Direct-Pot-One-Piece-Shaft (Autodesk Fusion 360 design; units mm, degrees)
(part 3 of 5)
sketch "Restore cam service opening after obsolete bore closure" plane through (23.9, 0, 0) normal (1, 0, 0) x axis (0, 0, -1)
  line L1 (-42.2047, 46.7373) -> (-43.8497, 47.5044)
  line L2 (-40.5875, 45.9133) -> (-42.2047, 46.7373)
  line L3 (-39, 45.0333) -> (-40.5875, 45.9133)
  line L4 (-37.4442, 44.0985) -> (-39, 45.0333)
  line L5 (-35.922, 43.11) -> (-37.4442, 44.0985)
  line L6 (-34.4352, 42.0689) -> (-35.922, 43.11)
  line L7 (-32.9856, 40.9766) -> (-34.4352, 42.0689)
  line L8 (-31.575, 39.8343) -> (-32.9856, 40.9766)
  line L9 (-30.2052, 38.6435) -> (-31.575, 39.8343)
  line L10 (-28.8778, 37.4057) -> (-30.2052, 38.6435)
  line L11 (-27.5943, 36.1222) -> (-28.8778, 37.4057)
  line L12 (-26.3565, 34.7948) -> (-27.5943, 36.1222)
  line L13 (-25.1657, 33.425) -> (-26.3565, 34.7948)
  line L14 (-24.0234, 32.0144) -> (-25.1657, 33.425)
  line L15 (-22.9311, 30.5648) -> (-24.0234, 32.0144)
  line L16 (-21.89, 29.078) -> (-22.9311, 30.5648)
  line L17 (-20.9015, 27.5558) -> (-21.89, 29.078)
  line L18 (-19.9667, 26) -> (-20.9015, 27.5558)
  line L19 (-19.0867, 24.4125) -> (-19.9667, 26)
  line L20 (-18.2627, 22.7953) -> (-19.0867, 24.4125)
  line L21 (-17.4956, 21.1503) -> (-18.2627, 22.7953)
  line L22 (-16.7864, 19.4795) -> (-17.4956, 21.1503)
  line L23 (-16.136, 17.785) -> (-16.7864, 19.4795)
  line L24 (-15.5451, 16.0689) -> (-16.136, 17.785)
  line L25 (-15.0144, 14.3331) -> (-15.5451, 16.0689)
  line L26 (-14.5446, 12.5799) -> (-15.0144, 14.3331)
  line L27 (-14.1363, 10.8114) -> (-14.5446, 12.5799)
  line L28 (-13.79, 9.0297) -> (-14.1363, 10.8114)
  line L29 (-13.5061, 7.237) -> (-13.79, 9.0297)
  line L30 (-13.2849, 5.4355) -> (-13.5061, 7.237)
  line L31 (-13.1267, 3.6273) -> (-13.2849, 5.4355)
  line L32 (-13.0317, 1.8148) -> (-13.1267, 3.6273)
  line L33 (-13, 0) -> (-13.0317, 1.8148)
  line L34 (-13.0317, -1.8148) -> (-13, 0)
  line L35 (-13.1267, -3.6273) -> (-13.0317, -1.8148)
  line L36 (-13.2849, -5.4355) -> (-13.1267, -3.6273)
  line L37 (-13.5061, -7.237) -> (-13.2849, -5.4355)
  line L38 (-13.79, -9.0297) -> (-13.5061, -7.237)
  line L39 (-14.1363, -10.8114) -> (-13.79, -9.0297)
  line L40 (-14.5446, -12.5799) -> (-14.1363, -10.8114)
  line L41 (-15.0144, -14.3331) -> (-14.5446, -12.5799)
  line L42 (-15.5451, -16.0689) -> (-15.0144, -14.3331)
  line L43 (-16.136, -17.785) -> (-15.5451, -16.0689)
  line L44 (-16.7864, -19.4795) -> (-16.136, -17.785)
  line L45 (-17.4956, -21.1503) -> (-16.7864, -19.4795)
  line L46 (-18.2627, -22.7953) -> (-17.4956, -21.1503)
  line L47 (-19.0867, -24.4125) -> (-18.2627, -22.7953)
  line L48 (-19.9667, -26) -> (-19.0867, -24.4125)
  line L49 (-20.9015, -27.5558) -> (-19.9667, -26)
  line L50 (-21.89, -29.078) -> (-20.9015, -27.5558)
  line L51 (-22.9311, -30.5648) -> (-21.89, -29.078)
  line L52 (-24.0234, -32.0144) -> (-22.9311, -30.5648)
  line L53 (-25.1657, -33.425) -> (-24.0234, -32.0144)
  line L54 (-26.3565, -34.7948) -> (-25.1657, -33.425)
  line L55 (-27.5943, -36.1222) -> (-26.3565, -34.7948)
  line L56 (-28.8778, -37.4057) -> (-27.5943, -36.1222)
  line L57 (-30.2052, -38.6435) -> (-28.8778, -37.4057)
  line L58 (-31.575, -39.8343) -> (-30.2052, -38.6435)
  line L59 (-32.9856, -40.9766) -> (-31.575, -39.8343)
  line L60 (-34.4352, -42.0689) -> (-32.9856, -40.9766)
  line L61 (-35.922, -43.11) -> (-34.4352, -42.0689)
  line L62 (-37.4442, -44.0985) -> (-35.922, -43.11)
  line L63 (-39, -45.0333) -> (-37.4442, -44.0985)
  line L64 (-40.5875, -45.9133) -> (-39, -45.0333)
  line L65 (-42.2047, -46.7373) -> (-40.5875, -45.9133)
  line L66 (-43.8497, -47.5044) -> (-42.2047, -46.7373)
  line L67 (-54.4248, -23.7522) -> (-43.8497, -47.5044)
  line L68 (-53.6024, -23.3686) -> (-54.4248, -23.7522)
  line L69 (-52.7937, -22.9566) -> (-53.6024, -23.3686)
  line L70 (-52, -22.5167) -> (-52.7937, -22.9566)
  line L71 (-51.2221, -22.0493) -> (-52, -22.5167)
  line L72 (-50.461, -21.555) -> (-51.2221, -22.0493)
  line L73 (-49.7176, -21.0344) -> (-50.461, -21.555)
  line L74 (-48.9928, -20.4883) -> (-49.7176, -21.0344)
  line L75 (-48.2875, -19.9172) -> (-48.9928, -20.4883)
  line L76 (-47.6026, -19.3218) -> (-48.2875, -19.9172)
  line L77 (-46.9389, -18.7028) -> (-47.6026, -19.3218)
  line L78 (-46.2972, -18.0611) -> (-46.9389, -18.7028)
  line L79 (-45.6782, -17.3974) -> (-46.2972, -18.0611)
  line L80 (-45.0828, -16.7125) -> (-45.6782, -17.3974)
  line L81 (-44.5117, -16.0072) -> (-45.0828, -16.7125)
  line L82 (-43.9656, -15.2824) -> (-44.5117, -16.0072)
  line L83 (-43.445, -14.539) -> (-43.9656, -15.2824)
  line L84 (-42.9507, -13.7779) -> (-43.445, -14.539)
  line L85 (-42.4833, -13) -> (-42.9507, -13.7779)
  line L86 (-42.0434, -12.2063) -> (-42.4833, -13)
  line L87 (-41.6314, -11.3976) -> (-42.0434, -12.2063)
  line L88 (-41.2478, -10.5752) -> (-41.6314, -11.3976)
  line L89 (-40.8932, -9.7398) -> (-41.2478, -10.5752)
  line L90 (-40.568, -8.8925) -> (-40.8932, -9.7398)
  line L91 (-40.2725, -8.0344) -> (-40.568, -8.8925)
  line L92 (-40.0072, -7.1666) -> (-40.2725, -8.0344)
  line L93 (-39.7723, -6.29) -> (-40.0072, -7.1666)
  line L94 (-39.5682, -5.4057) -> (-39.7723, -6.29)
  line L95 (-39.395, -4.5149) -> (-39.5682, -5.4057)
  line L96 (-39.253, -3.6185) -> (-39.395, -4.5149)
  line L97 (-39.1424, -2.7177) -> (-39.253, -3.6185)
  line L98 (-39.0633, -1.8137) -> (-39.1424, -2.7177)
  line L99 (-39.0158, -0.9074) -> (-39.0633, -1.8137)
  line L100 (-39, 0) -> (-39.0158, -0.9074)
  line L101 (-39.0158, 0.9074) -> (-39, 0)
  line L102 (-39.0633, 1.8137) -> (-39.0158, 0.9074)
  line L103 (-39.1424, 2.7177) -> (-39.0633, 1.8137)
  line L104 (-39.253, 3.6185) -> (-39.1424, 2.7177)
  line L105 (-39.395, 4.5149) -> (-39.253, 3.6185)
  line L106 (-39.5682, 5.4057) -> (-39.395, 4.5149)
  line L107 (-39.7723, 6.29) -> (-39.5682, 5.4057)
  line L108 (-40.0072, 7.1666) -> (-39.7723, 6.29)
  line L109 (-40.2725, 8.0344) -> (-40.0072, 7.1666)
  line L110 (-40.568, 8.8925) -> (-40.2725, 8.0344)
  line L111 (-40.8932, 9.7398) -> (-40.568, 8.8925)
  line L112 (-41.2478, 10.5752) -> (-40.8932, 9.7398)
  line L113 (-41.6314, 11.3976) -> (-41.2478, 10.5752)
  line L114 (-42.0434, 12.2063) -> (-41.6314, 11.3976)
  line L115 (-42.4833, 13) -> (-42.0434, 12.2063)
  line L116 (-42.9507, 13.7779) -> (-42.4833, 13)
  line L117 (-43.445, 14.539) -> (-42.9507, 13.7779)
  line L118 (-43.9656, 15.2824) -> (-43.445, 14.539)
  line L119 (-44.5117, 16.0072) -> (-43.9656, 15.2824)
  line L120 (-45.0828, 16.7125) -> (-44.5117, 16.0072)
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extrude "Extrude47" cut sketch "Restore cam service opening after obsolete bore closure" along normal blind 12.2
work_plane "WorkPlane48" AlongDistance -15.4 ExtraOffset 0
sketch "Fill former M5 stop nut pocket" plane through (-15.4, 0, 0) normal (1, 0, 0) x axis (0, 0, -1)
  circle C1 centre (-79.6754, -33.9652) radius 4.9
extrude "Extrude48" add sketch "Fill former M5 stop nut pocket" along normal blind 6.4
work_plane "WorkPlane49" AlongDistance -36 ExtraOffset 0
sketch "Fill former M5 stop bore" plane through (-36, 0, 0) normal (1, 0, 0) x axis (0, 0, -1)
  circle C1 centre (-79.6754, -33.9652) radius 2.71
extrude "Extrude49" add sketch "Fill former M5 stop bore" along normal blind 27
work_plane "WorkPlane50" AlongDistance -36.1 ExtraOffset 0
sketch "M3 stop reinforcement bore" plane through (-36.1, 0, 0) normal (1, 0, 0) x axis (0, 0, -1)
  circle C1 centre (-79.6754, -33.9652) radius 1.7
extrude "Extrude50" cut sketch "M3 stop reinforcement bore" along normal blind 27.2
work_plane "WorkPlane51" AlongDistance -13.5 ExtraOffset 0
sketch "Captive M3 locknut stop pocket" plane through (-13.5, 0, 0) normal (1, 0, 0) x axis (0, 0, -1)
  line L1 (-82.5754, -32.2908) -> (-79.6754, -30.6165)
  line L2 (-82.5754, -35.6395) -> (-82.5754, -32.2908)
  line L3 (-79.6754, -37.3138) -> (-82.5754, -35.6395)
  line L4 (-76.7754, -35.6395) -> (-79.6754, -37.3138)
  line L5 (-76.7754, -32.2908) -> (-76.7754, -35.6395)
  line L6 (-79.6754, -30.6165) -> (-76.7754, -32.2908)
extrude "Extrude51" cut sketch "Captive M3 locknut stop pocket" along normal blind 4.6
work_plane "WorkPlane52" AlongDistance -15.4 ExtraOffset 0
sketch "Fill former M5 stop nut pocket (1)" plane through (-15.4, 0, 0) normal (1, 0, 0) x axis (0, 0, -1)
  circle C1 centre (-79.6754, 33.9652) radius 4.9
extrude "Extrude52" add sketch "Fill former M5 stop nut pocket (1)" along normal blind 6.4
work_plane "WorkPlane53" AlongDistance -36 ExtraOffset 0
sketch "Fill former M5 stop bore (1)" plane through (-36, 0, 0) normal (1, 0, 0) x axis (0, 0, -1)
  circle C1 centre (-79.6754, 33.9652) radius 2.71
extrude "Extrude53" add sketch "Fill former M5 stop bore (1)" along normal blind 27
work_plane "WorkPlane54" AlongDistance -36.1 ExtraOffset 0
sketch "M3 stop reinforcement bore (1)" plane through (-36.1, 0, 0) normal (1, 0, 0) x axis (0, 0, -1)
  circle C1 centre (-79.6754, 33.9652) radius 1.7
extrude "Extrude54" cut sketch "M3 stop reinforcement bore (1)" along normal blind 27.2
work_plane "WorkPlane55" AlongDistance -13.5 ExtraOffset 0
sketch "Captive M3 locknut stop pocket (1)" plane through (-13.5, 0, 0) normal (1, 0, 0) x axis (0, 0, -1)
  line L1 (-82.5754, 35.6395) -> (-79.6754, 37.3138)
  line L2 (-82.5754, 32.2908) -> (-82.5754, 35.6395)
  line L3 (-79.6754, 30.6165) -> (-82.5754, 32.2908)
  line L4 (-76.7754, 32.2908) -> (-79.6754, 30.6165)
  line L5 (-76.7754, 35.6395) -> (-76.7754, 32.2908)
  line L6 (-79.6754, 37.3138) -> (-76.7754, 35.6395)
extrude "Extrude55" cut sketch "Captive M3 locknut stop pocket (1)" along normal blind 4.6
work_plane "WorkPlane56" AlongDistance -17.5 ExtraOffset 0
sketch "Recess M3 locknut to keep bolt inside stop" plane through (-17.5, 0, 0) normal (1, 0, 0) x axis (0, 0, -1)
  line L1 (-82.5754, -32.2908) -> (-79.6754, -30.6165)
  line L2 (-82.5754, -35.6395) -> (-82.5754, -32.2908)
  line L3 (-79.6754, -37.3138) -> (-82.5754, -35.6395)
  line L4 (-76.7754, -35.6395) -> (-79.6754, -37.3138)
  line L5 (-76.7754, -32.2908) -> (-76.7754, -35.6395)
  line L6 (-79.6754, -30.6165) -> (-76.7754, -32.2908)
extrude "Extrude56" cut sketch "Recess M3 locknut to keep bolt inside stop" along normal blind 4.01
work_plane "WorkPlane57" AlongDistance -17.5 ExtraOffset 0
sketch "Recess M3 locknut to keep bolt inside stop (1)" plane through (-17.5, 0, 0) normal (1, 0, 0) x axis (0, 0, -1)
  line L1 (-82.5754, 35.6395) -> (-79.6754, 37.3138)
  line L2 (-82.5754, 32.2908) -> (-82.5754, 35.6395)
  line L3 (-79.6754, 30.6165) -> (-82.5754, 32.2908)
  line L4 (-76.7754, 32.2908) -> (-79.6754, 30.6165)
  line L5 (-76.7754, 35.6395) -> (-76.7754, 32.2908)
  line L6 (-79.6754, 37.3138) -> (-76.7754, 35.6395)
extrude "Extrude57" cut sketch "Recess M3 locknut to keep bolt inside stop (1)" along normal blind 4.01
work_plane "WorkPlane6" AlongDistance -7.2 ExtraOffset 0
sketch "Upright socket roof 45 degrees" plane through (0, -7.2, 0) normal (0, 1, 0) x axis (1, 0, 0)
  line L1 (-7.2, -196) -> (0, -196)
  line L2 (0, -203.2) -> (-7.2, -196)
  line L3 (0, -196) -> (0, -203.2)
extrude "Extrude5" cut sketch "Upright socket roof 45 degrees" along normal blind 14.4
work_plane "WorkPlane8" AlongDistance -7.2 ExtraOffset 0
sketch "Upright socket roof 45 degrees" plane through (0, -7.2, 0) normal (0, 1, 0) x axis (1, 0, 0)
  line L1 (7.2, -196) -> (0, -196)
  line L2 (0, -203.2) -> (7.2, -196)
  line L3 (0, -196) -> (0, -203.2)
extrude "Extrude7" cut sketch "Upright socket roof 45 degrees" along normal blind 14.4
work_plane "WorkPlane58" AlongDistance -36 ExtraOffset 0
sketch "Stock M5x14 mounting seat Z64" plane through (-36, 0, 0) normal (1, 0, 0) x axis (0, 0, -1)
  line L1 (-63, -70) -> (-63, -95)
  line L2 (-64, -70) -> (-63, -70)
  line L3 (-64, -95) -> (-64, -70)
  line L4 (-63, -95) -> (-64, -95)
extrude "Extrude58" add sketch "Stock M5x14 mounting seat Z64" along normal blind 12
work_plane "WorkPlane59" AlongDistance 62.9 ExtraOffset 0
sketch "Continue rail clearance through new seat" plane through (0, 0, 62.9) normal (0, 0, 1) x axis (1, 0, 0)
  circle C1 centre (-30, -85) radius 2.7
extrude "Extrude59" cut sketch "Continue rail clearance through new seat" along normal blind 1.2
work_plane "WorkPlane1" AlongDistance 50 ExtraOffset 0
sketch "Rail M5x14 DIN912 (-30, -1)" plane through (0, 0, 50) normal (0, 0, 1) x axis (1, 0, 0)
  circle C1 centre (-30, -85) radius 2.5
extrude "Extrude1" new body sketch "Rail M5x14 DIN912 (-30, -1)" along normal blind 14 bodies "HARDWARE Rail M5x14 DIN912 (-30, -1)"
work_plane "WorkPlane2" AlongDistance 64 ExtraOffset 0
sketch "Button head" plane through (0, 0, 64) normal (0, 0, 1) x axis (1, 0, 0)
  circle C1 centre (-30, -85) radius 4.25
extrude "Extrude2" add sketch "Button head" along normal blind 5
work_plane "WorkPlane60" AlongDistance -36 ExtraOffset 0
sketch "Stock M5x14 mounting seat Z64 (1)" plane through (-36, 0, 0) normal (1, 0, 0) x axis (0, 0, -1)
  line L1 (-63, 95) -> (-63, 70)
  line L2 (-64, 95) -> (-63, 95)
  line L3 (-64, 70) -> (-64, 95)
  line L4 (-63, 70) -> (-64, 70)
extrude "Extrude60" add sketch "Stock M5x14 mounting seat Z64 (1)" along normal blind 12
work_plane "WorkPlane61" AlongDistance 62.9 ExtraOffset 0
sketch "Continue rail clearance through new seat (1)" plane through (0, 0, 62.9) normal (0, 0, 1) x axis (1, 0, 0)
  circle C1 centre (-30, 85) radius 2.7
extrude "Extrude61" cut sketch "Continue rail clearance through new seat (1)" along normal blind 1.2
work_plane "WorkPlane1" AlongDistance 50 ExtraOffset 0
sketch "Rail M5x14 DIN912 (-30, 1)" plane through (0, 0, 50) normal (0, 0, 1) x axis (1, 0, 0)
  circle C1 centre (-30, 85) radius 2.5
extrude "Extrude1" new body sketch "Rail M5x14 DIN912 (-30, 1)" along normal blind 14 bodies "HARDWARE Rail M5x14 DIN912 (-30, 1)"
work_plane "WorkPlane2" AlongDistance 64 ExtraOffset 0
sketch "Button head" plane through (0, 0, 64) normal (0, 0, 1) x axis (1, 0, 0)
  circle C1 centre (-30, 85) radius 4.25
extrude "Extrude2" add sketch "Button head" along normal blind 5
work_plane "WorkPlane62" AlongDistance -36 ExtraOffset 0
sketch "Close obsolete long pivot screw hole" plane through (-36, 0, 0) normal (1, 0, 0) x axis (0, 0, -1)
  circle C1 centre (-12, -35) radius 1.71
extrude "Extrude62" add sketch "Close obsolete long pivot screw hole" along normal blind 12
work_plane "WorkPlane63" AlongDistance -26 ExtraOffset 0
sketch "Blind captive printed pivot seat" plane through (-26, 0, 0) normal (1, 0, 0) x axis (0, 0, -1)
  circle C1 centre (-12, -35) radius 4.15
extrude "Extrude63" cut sketch "Blind captive printed pivot seat" along normal blind 2.1
work_plane "WorkPlane48" AlongDistance 24 ExtraOffset 0
sketch "Stock M5x14 mounting seat Z64" plane through (24, 0, 0) normal (1, 0, 0) x axis (0, 0, -1)
  line L1 (-63, -70) -> (-63, -95)
  line L2 (-64, -70) -> (-63, -70)
  line L3 (-64, -95) -> (-64, -70)
  line L4 (-63, -95) -> (-64, -95)
extrude "Extrude48" add sketch "Stock M5x14 mounting seat Z64" along normal blind 12
work_plane "WorkPlane49" AlongDistance 62.9 ExtraOffset 0
sketch "Continue rail clearance through new seat" plane through (0, 0, 62.9) normal (0, 0, 1) x axis (1, 0, 0)
  circle C1 centre (30, -85) radius 2.7
extrude "Extrude49" cut sketch "Continue rail clearance through new seat" along normal blind 1.2
work_plane "WorkPlane1" AlongDistance 50 ExtraOffset 0
sketch "Rail M5x14 DIN912 (30, -1)" plane through (0, 0, 50) normal (0, 0, 1) x axis (1, 0, 0)
  circle C1 centre (30, -85) radius 2.5
extrude "Extrude1" new body sketch "Rail M5x14 DIN912 (30, -1)" along normal blind 14 bodies "HARDWARE Rail M5x14 DIN912 (30, -1)"
work_plane "WorkPlane2" AlongDistance 64 ExtraOffset 0
sketch "Button head" plane through (0, 0, 64) normal (0, 0, 1) x axis (1, 0, 0)
  circle C1 centre (30, -85) radius 4.25
extrude "Extrude2" add sketch "Button head" along normal blind 5
work_plane "WorkPlane50" AlongDistance 24 ExtraOffset 0
sketch "Stock M5x14 mounting seat Z64 (1)" plane through (24, 0, 0) normal (1, 0, 0) x axis (0, 0, -1)
  line L1 (-63, 95) -> (-63, 70)
  line L2 (-64, 95) -> (-63, 95)
  line L3 (-64, 70) -> (-64, 95)
  line L4 (-63, 70) -> (-64, 70)
extrude "Extrude50" add sketch "Stock M5x14 mounting seat Z64 (1)" along normal blind 12
work_plane "WorkPlane51" AlongDistance 62.9 ExtraOffset 0
sketch "Continue rail clearance through new seat (1)" plane through (0, 0, 62.9) normal (0, 0, 1) x axis (1, 0, 0)
  circle C1 centre (30, 85) radius 2.7
extrude "Extrude51" cut sketch "Continue rail clearance through new seat (1)" along normal blind 1.2
work_plane "WorkPlane1" AlongDistance 50 ExtraOffset 0
sketch "Rail M5x14 DIN912 (30, 1)" plane through (0, 0, 50) normal (0, 0, 1) x axis (1, 0, 0)
  circle C1 centre (30, 85) radius 2.5
extrude "Extrude1" new body sketch "Rail M5x14 DIN912 (30, 1)" along normal blind 14 bodies "HARDWARE Rail M5x14 DIN912 (30, 1)"
work_plane "WorkPlane2" AlongDistance 64 ExtraOffset 0
sketch "Button head" plane through (0, 0, 64) normal (0, 0, 1) x axis (1, 0, 0)
  circle C1 centre (30, 85) radius 4.25
extrude "Extrude2" add sketch "Button head" along normal blind 5
work_plane "WorkPlane52" AlongDistance 24 ExtraOffset 0
sketch "Close obsolete long pivot screw hole" plane through (24, 0, 0) normal (1, 0, 0) x axis (0, 0, -1)
  circle C1 centre (-12, -35) radius 1.71
extrude "Extrude52" add sketch "Close obsolete long pivot screw hole" along normal blind 12
work_plane "WorkPlane53" AlongDistance 23.9 ExtraOffset 0
sketch "Blind captive printed pivot seat" plane through (23.9, 0, 0) normal (1, 0, 0) x axis (0, 0, -1)
  circle C1 centre (-12, -35) radius 4.15
extrude "Extrude53" cut sketch "Blind captive printed pivot seat" along normal blind 2.1
work_plane "WorkPlane1" AlongDistance -25.85 ExtraOffset 0
sketch "Captured axle 0.3 mm total end clearance" plane through (-25.85, 0, 0) normal (1, 0, 0) x axis (0, 0, -1)
  circle C1 centre (-12, -35) radius 4
extrude "Extrude1" new body sketch "Captured axle 0.3 mm total end clearance" along normal blind 51.7 bodies "P25 Captured printed pivot lower half"
work_plane "WorkPlane2" AlongDistance -26 ExtraOffset 0
sketch "Longitudinal flat print face" plane through (-26, 0, 0) normal (1, 0, 0) x axis (0, 0, -1)
  line L1 (-7, -30) -> (-7, -35)
  line L2 (-17, -30) -> (-7, -30)
  line L3 (-17, -35) -> (-17, -30)
  line L4 (-7, -35) -> (-17, -35)
extrude "Extrude2" cut sketch "Longitudinal flat print face" along normal blind 52
work_plane "WorkPlane1" AlongDistance -25.85 ExtraOffset 0
sketch "Captured axle 0.3 mm total end clearance" plane through (-25.85, 0, 0) normal (1, 0, 0) x axis (0, 0, -1)
  circle C1 centre (-12, -35) radius 4
extrude "Extrude1" new body sketch "Captured axle 0.3 mm total end clearance" along normal blind 51.7 bodies "P26 Captured printed pivot upper half"
work_plane "WorkPlane2" AlongDistance -26 ExtraOffset 0
sketch "Longitudinal flat print face" plane through (-26, 0, 0) normal (1, 0, 0) x axis (0, 0, -1)
  line L1 (-7, -35) -> (-7, -40)
  line L2 (-17, -35) -> (-7, -35)
  line L3 (-17, -40) -> (-17, -35)
  line L4 (-7, -40) -> (-17, -40)
extrude "Extrude2" cut sketch "Longitudinal flat print face" along normal blind 52
work_plane "WorkPlane9" AlongDistance 9 ExtraOffset 0
sketch "Recess for stocked M3x20 grip screw" plane through (9, 0, 0) normal (1, 0, 0) x axis (0, 0, -1)
  circle C1 centre (-180, 0) radius 3.1
extrude "Extrude8" cut sketch "Recess for stocked M3x20 grip screw" along normal blind 3.6
work_plane "WorkPlane1" AlongDistance -11 ExtraOffset 0
sketch "Grip M3x20 cap head 180" plane through (-11, 0, 0) normal (1, 0, 0) x axis (0, 0, -1)
  circle C1 centre (-180, 0) radius 1.5
extrude "Extrude1" new body sketch "Grip M3x20 cap head 180" along normal blind 20 bodies "HARDWARE Grip M3x20 cap head 180"
work_plane "WorkPlane2" AlongDistance 9 ExtraOffset 0
sketch "Button head" plane through (9, 0, 0) normal (1, 0, 0) x axis (0, 0, -1)
  circle C1 centre (-180, 0) radius 2.75
extrude "Extrude2" add sketch "Button head" along normal blind 3
work_plane "WorkPlane10" AlongDistance 9 ExtraOffset 0
sketch "Recess for stocked M3x20 grip screw (1)" plane through (9, 0, 0) normal (1, 0, 0) x axis (0, 0, -1)
  circle C1 centre (-190, 0) radius 3.1
extrude "Extrude9" cut sketch "Recess for stocked M3x20 grip screw (1)" along normal blind 3.6
work_plane "WorkPlane1" AlongDistance -11 ExtraOffset 0
sketch "Grip M3x20 cap head 190" plane through (-11, 0, 0) normal (1, 0, 0) x axis (0, 0, -1)
  circle C1 centre (-190, 0) radius 1.5
extrude "Extrude1" new body sketch "Grip M3x20 cap head 190" along normal blind 20 bodies "HARDWARE Grip M3x20 cap head 190"
work_plane "WorkPlane2" AlongDistance 9 ExtraOffset 0
sketch "Button head" plane through (9, 0, 0) normal (1, 0, 0) x axis (0, 0, -1)
  circle C1 centre (-190, 0) radius 2.75
extrude "Extrude2" add sketch "Button head" along normal blind 3
work_plane "WorkPlane64" AlongDistance -36.1 ExtraOffset 0
sketch "Stock M3x20 stop recessed cap head" plane through (-36.1, 0, 0) normal (1, 0, 0) x axis (0, 0, -1)
  circle C1 centre (-79.6754, -33.9652) radius 3.1
extrude "Extrude64" cut sketch "Stock M3x20 stop recessed cap head" along normal blind 4.6
work_plane "WorkPlane1" AlongDistance -31.5 ExtraOffset 0
sketch "Stop M3x20 cap head -1" plane through (-31.5, 0, 0) normal (1, 0, 0) x axis (0, 0, -1)
  circle C1 centre (-79.6754, -33.9652) radius 1.5
extrude "Extrude1" new body sketch "Stop M3x20 cap head -1" along normal blind 20 bodies "HARDWARE Stop M3x20 cap head -1"
work_plane "WorkPlane2" AlongDistance -34.5 ExtraOffset 0
sketch "Button head" plane through (-34.5, 0, 0) normal (1, 0, 0) x axis (0, 0, -1)
  circle C1 centre (-79.6754, -33.9652) radius 2.75
extrude "Extrude2" add sketch "Button head" along normal blind 3
work_plane "WorkPlane1" AlongDistance -17.5 ExtraOffset 0
sketch "Stop M3 plain captive nut -1" plane through (-17.5, 0, 0) normal (1, 0, 0) x axis (0, 0, -1)
  line L1 (-82.4254, -32.3774) -> (-79.6754, -30.7897)
  line L2 (-82.4254, -35.5529) -> (-82.4254, -32.3774)
  line L3 (-79.6754, -37.1406) -> (-82.4254, -35.5529)
  line L4 (-76.9254, -35.5529) -> (-79.6754, -37.1406)
  line L5 (-76.9254, -32.3774) -> (-76.9254, -35.5529)
  line L6 (-79.6754, -30.7897) -> (-76.9254, -32.3774)
extrude "Extrude1" new body sketch "Stop M3 plain captive nut -1" along normal blind 2.4 bodies "HARDWARE Stop M3 plain captive nut -1"
work_plane "WorkPlane2" AlongDistance -17.6 ExtraOffset 0
sketch "Thread envelope" plane through (-17.6, 0, 0) normal (1, 0, 0) x axis (0, 0, -1)
  circle C1 centre (-79.6754, -33.9652) radius 1.5
extrude "Extrude2" cut sketch "Thread envelope" along normal blind 2.6
work_plane "WorkPlane65" AlongDistance -36.1 ExtraOffset 0
sketch "Stock M3x20 stop recessed cap head (1)" plane through (-36.1, 0, 0) normal (1, 0, 0) x axis (0, 0, -1)
  circle C1 centre (-79.6754, 33.9652) radius 3.1
extrude "Extrude65" cut sketch "Stock M3x20 stop recessed cap head (1)" along normal blind 4.6
work_plane "WorkPlane1" AlongDistance -31.5 ExtraOffset 0
sketch "Stop M3x20 cap head 1" plane through (-31.5, 0, 0) normal (1, 0, 0) x axis (0, 0, -1)
  circle C1 centre (-79.6754, 33.9652) radius 1.5
extrude "Extrude1" new body sketch "Stop M3x20 cap head 1" along normal blind 20 bodies "HARDWARE Stop M3x20 cap head 1"
work_plane "WorkPlane2" AlongDistance -34.5 ExtraOffset 0
sketch "Button head" plane through (-34.5, 0, 0) normal (1, 0, 0) x axis (0, 0, -1)
  circle C1 centre (-79.6754, 33.9652) radius 2.75
extrude "Extrude2" add sketch "Button head" along normal blind 3
work_plane "WorkPlane1" AlongDistance -17.5 ExtraOffset 0
sketch "Stop M3 plain captive nut 1" plane through (-17.5, 0, 0) normal (1, 0, 0) x axis (0, 0, -1)
  line L1 (-82.4254, 35.5529) -> (-79.6754, 37.1406)
  line L2 (-82.4254, 32.3774) -> (-82.4254, 35.5529)
  line L3 (-79.6754, 30.7897) -> (-82.4254, 32.3774)
  line L4 (-76.9254, 32.3774) -> (-79.6754, 30.7897)
  line L5 (-76.9254, 35.5529) -> (-76.9254, 32.3774)
  line L6 (-79.6754, 37.1406) -> (-76.9254, 35.5529)
extrude "Extrude1" new body sketch "Stop M3 plain captive nut 1" along normal blind 2.4 bodies "HARDWARE Stop M3 plain captive nut 1"
work_plane "WorkPlane2" AlongDistance -17.6 ExtraOffset 0
sketch "Thread envelope" plane through (-17.6, 0, 0) normal (1, 0, 0) x axis (0, 0, -1)
  circle C1 centre (-79.6754, 33.9652) radius 1.5
extrude "Extrude2" cut sketch "Thread envelope" along normal blind 2.6
work_plane "WorkPlane10" AlongDistance 7 ExtraOffset 0
sketch "Bearing inner race support pad" plane through (7, 0, 0) normal (1, 0, 0) x axis (0, 0, -1)
  circle C1 centre (-12, 0) radius 2.4
extrude "Extrude10" add sketch "Bearing inner race support pad" along normal blind 1
work_plane "WorkPlane11" AlongDistance 6.9 ExtraOffset 0
sketch "Preserve roller screw clearance" plane through (6.9, 0, 0) normal (1, 0, 0) x axis (0, 0, -1)
  circle C1 centre (-12, 0) radius 1.7
extrude "Extrude11" cut sketch "Preserve roller screw clearance" along normal blind 1.2
work_plane "WorkPlane12" AlongDistance 16 ExtraOffset 0
sketch "Bearing inner race support pad (1)" plane through (16, 0, 0) normal (1, 0, 0) x axis (0, 0, -1)
  circle C1 centre (-12, 0) radius 2.4
extrude "Extrude12" add sketch "Bearing inner race support pad (1)" along normal blind 1
work_plane "WorkPlane13" AlongDistance 15.9 ExtraOffset 0
sketch "Preserve roller screw clearance (1)" plane through (15.9, 0, 0) normal (1, 0, 0) x axis (0, 0, -1)
  circle C1 centre (-12, 0) radius 1.7
extrude "Extrude13" cut sketch "Preserve roller screw clearance (1)" along normal blind 1.2
work_plane "WorkPlane1" AlongDistance 8 ExtraOffset 0
sketch "Stock 623ZZ envelope 3x10x4" plane through (8, 0, 0) normal (1, 0, 0) x axis (0, 0, -1)
  circle C1 centre (-12, 0) radius 5
extrude "Extrude1" new body sketch "Stock 623ZZ envelope 3x10x4" along normal blind 4 bodies "HARDWARE 623ZZ roller bearing at 8"
work_plane "WorkPlane2" AlongDistance 7.9 ExtraOffset 0
sketch "Bearing inner race bore" plane through (7.9, 0, 0) normal (1, 0, 0) x axis (0, 0, -1)
  circle C1 centre (-12, 0) radius 1.5
extrude "Extrude2" cut sketch "Bearing inner race bore" along normal blind 4.2
work_plane "WorkPlane1" AlongDistance 12 ExtraOffset 0
sketch "Stock 623ZZ envelope 3x10x4" plane through (12, 0, 0) normal (1, 0, 0) x axis (0, 0, -1)
  circle C1 centre (-12, 0) radius 5
extrude "Extrude1" new body sketch "Stock 623ZZ envelope 3x10x4" along normal blind 4 bodies "HARDWARE 623ZZ roller bearing at 12"
work_plane "WorkPlane2" AlongDistance 11.9 ExtraOffset 0
sketch "Bearing inner race bore" plane through (11.9, 0, 0) normal (1, 0, 0) x axis (0, 0, -1)
  circle C1 centre (-12, 0) radius 1.5
extrude "Extrude2" cut sketch "Bearing inner race bore" along normal blind 4.2
work_plane "WorkPlane45" AlongDistance 38 ExtraOffset 0
sketch "Close former long guide bore" plane through (0, 0, 38) normal (0, 0, 1) x axis (1, 0, 0)
  circle C1 centre (5, -55) radius 1.71
extrude "Extrude45" add sketch "Close former long guide bore" along normal blind 21
work_plane "WorkPlane46" AlongDistance 38 ExtraOffset 0
sketch "Close former long guide bore (1)" plane through (0, 0, 38) normal (0, 0, 1) x axis (1, 0, 0)
  circle C1 centre (19, -55) radius 1.71
extrude "Extrude46" add sketch "Close former long guide bore (1)" along normal blind 21
work_plane "WorkPlane47" AlongDistance 38 ExtraOffset 0
sketch "Close obsolete M4 nut pocket" plane through (0, 0, 38) normal (0, 0, 1) x axis (1, 0, 0)
  line L1 (14.1362, -51.3) -> (16.2724, -55)
  line L2 (9.8638, -51.3) -> (14.1362, -51.3)
  line L3 (7.7276, -55) -> (9.8638, -51.3)
  line L4 (9.8638, -58.7) -> (7.7276, -55)
  line L5 (14.1362, -58.7) -> (9.8638, -58.7)
  line L6 (16.2724, -55) -> (14.1362, -58.7)
extrude "Extrude47" add sketch "Close obsolete M4 nut pocket" along normal blind 3.5
work_plane "WorkPlane48" AlongDistance 38 ExtraOffset 0
sketch "Close obsolete M4 adjuster passage" plane through (0, 0, 38) normal (0, 0, 1) x axis (1, 0, 0)
  circle C1 centre (12, -55) radius 2.21
extrude "Extrude48" add sketch "Close obsolete M4 adjuster passage" along normal blind 21
work_plane "WorkPlane49" AlongDistance 37.9 ExtraOffset 0
sketch "M3 preload adjuster passage" plane through (0, 0, 37.9) normal (0, 0, 1) x axis (1, 0, 0)
  circle C1 centre (12, -55) radius 1.7
extrude "Extrude49" cut sketch "M3 preload adjuster passage" along normal blind 21.2
work_plane "WorkPlane50" AlongDistance 37.9 ExtraOffset 0
sketch "M3 preload insert from spring side" plane through (0, 0, 37.9) normal (0, 0, 1) x axis (1, 0, 0)
  circle C1 centre (12, -55) radius 2
extrude "Extrude50" cut sketch "M3 preload insert from spring side" along normal blind 6.9
work_plane "WorkPlane51" AlongDistance 55 ExtraOffset 0
sketch "Recessed preload head and limiter access" plane through (0, 0, 55) normal (0, 0, 1) x axis (1, 0, 0)
  circle C1 centre (12, -55) radius 3.4
extrude "Extrude51" cut sketch "Recessed preload head and limiter access" along normal blind 4.1
work_plane "WorkPlane52" AlongDistance 37.9 ExtraOffset 0
sketch "Short guide M3 insert from underside" plane through (0, 0, 37.9) normal (0, 0, 1) x axis (1, 0, 0)
  circle C1 centre (4, -55) radius 2
extrude "Extrude52" cut sketch "Short guide M3 insert from underside" along normal blind 6.9
work_plane "WorkPlane1" AlongDistance 32 ExtraOffset 0
sketch "Short compression sleeve" plane through (0, 0, 32) normal (0, 0, 1) x axis (1, 0, 0)
  circle C1 centre (4, -55) radius 2.5
extrude "Extrude1" new body sketch "Short compression sleeve" along normal blind 6 bodies "P27 Printed guide sleeve 4"
work_plane "WorkPlane2" AlongDistance 31.9 ExtraOffset 0
sketch "Guide screw bore" plane through (0, 0, 31.9) normal (0, 0, 1) x axis (1, 0, 0)
  circle C1 centre (4, -55) radius 1.65
extrude "Extrude2" cut sketch "Guide screw bore" along normal blind 6.2
work_plane "WorkPlane1" AlongDistance 32 ExtraOffset 0
sketch "Cup guide M3x12 4" plane through (0, 0, 32) normal (0, 0, 1) x axis (1, 0, 0)
  circle C1 centre (4, -55) radius 1.5
extrude "Extrude1" new body sketch "Cup guide M3x12 4" along normal blind 12 bodies "HARDWARE Cup guide M3x12 4"
work_plane "WorkPlane2" AlongDistance 29 ExtraOffset 0
sketch "Button head" plane through (0, 0, 29) normal (0, 0, 1) x axis (1, 0, 0)
  circle C1 centre (4, -55) radius 2.75
extrude "Extrude2" add sketch "Button head" along normal blind 3
work_plane "WorkPlane53" AlongDistance 37.9 ExtraOffset 0
sketch "Short guide M3 insert from underside (1)" plane through (0, 0, 37.9) normal (0, 0, 1) x axis (1, 0, 0)
  circle C1 centre (20, -55) radius 2
extrude "Extrude53" cut sketch "Short guide M3 insert from underside (1)" along normal blind 6.9
work_plane "WorkPlane1" AlongDistance 32 ExtraOffset 0
sketch "Short compression sleeve" plane through (0, 0, 32) normal (0, 0, 1) x axis (1, 0, 0)
  circle C1 centre (20, -55) radius 2.5
extrude "Extrude1" new body sketch "Short compression sleeve" along normal blind 6 bodies "P27 Printed guide sleeve 20"
work_plane "WorkPlane2" AlongDistance 31.9 ExtraOffset 0
sketch "Guide screw bore" plane through (0, 0, 31.9) normal (0, 0, 1) x axis (1, 0, 0)
  circle C1 centre (20, -55) radius 1.65
extrude "Extrude2" cut sketch "Guide screw bore" along normal blind 6.2
work_plane "WorkPlane1" AlongDistance 32 ExtraOffset 0
sketch "Cup guide M3x12 20" plane through (0, 0, 32) normal (0, 0, 1) x axis (1, 0, 0)
  circle C1 centre (20, -55) radius 1.5
extrude "Extrude1" new body sketch "Cup guide M3x12 20" along normal blind 12 bodies "HARDWARE Cup guide M3x12 20"
work_plane "WorkPlane2" AlongDistance 29 ExtraOffset 0
sketch "Button head" plane through (0, 0, 29) normal (0, 0, 1) x axis (1, 0, 0)
  circle C1 centre (20, -55) radius 2.75
extrude "Extrude2" add sketch "Button head" along normal blind 3
work_plane "WorkPlane1" AlongDistance 0.2 ExtraOffset 0
sketch "Wide stock spring seat" plane through (0.2, 0, 0) normal (1, 0, 0) x axis (0, 0, -1)
  line L1 (-35, -49) -> (-35, -61)
  line L2 (-37, -49) -> (-35, -49)
  line L3 (-37, -61) -> (-37, -49)
  line L4 (-35, -61) -> (-37, -61)
extrude "Extrude1" new body sketch "Wide stock spring seat" along normal blind 23.6 bodies "P14 Captive spring cup for 9 mm spring"
work_plane "WorkPlane2" AlongDistance 29 ExtraOffset 0
sketch "Provisional 6 mm spring pilot" plane through (0, 0, 29) normal (0, 0, 1) x axis (1, 0, 0)
  circle C1 centre (12, -55) radius 3
extrude "Extrude2" add sketch "Provisional 6 mm spring pilot" along normal blind 6
work_plane "WorkPlane3" AlongDistance 34.9 ExtraOffset 0
sketch "Printed guide running clearance" plane through (0, 0, 34.9) normal (0, 0, 1) x axis (1, 0, 0)
  circle C1 centre (4, -55) radius 2.7
extrude "Extrude3" cut sketch "Printed guide running clearance" along normal blind 2.2
work_plane "WorkPlane4" AlongDistance 34.9 ExtraOffset 0
sketch "Printed guide running clearance (1)" plane through (0, 0, 34.9) normal (0, 0, 1) x axis (1, 0, 0)
  circle C1 centre (20, -55) radius 2.7
extrude "Extrude4" cut sketch "Printed guide running clearance (1)" along normal blind 2.2
work_plane "WorkPlane1" AlongDistance 55 ExtraOffset 0
sketch "Preserve one mm additional compression limit" plane through (0, 0, 55) normal (0, 0, 1) x axis (1, 0, 0)
  circle C1 centre (12, -55) radius 3.2
extrude "Extrude1" new body sketch "Preserve one mm additional compression limit" along normal blind 2 bodies "P15 Recessed preload limit collar 1 mm"
work_plane "WorkPlane2" AlongDistance 54.9 ExtraOffset 0
sketch "M3 adjuster clearance" plane through (0, 0, 54.9) normal (0, 0, 1) x axis (1, 0, 0)
  circle C1 centre (12, -55) radius 1.7
extrude "Extrude2" cut sketch "M3 adjuster clearance" along normal blind 2.2
work_plane "WorkPlane1" AlongDistance 37 ExtraOffset 0
sketch "Preload M3x20 cap head" plane through (0, 0, 37) normal (0, 0, 1) x axis (1, 0, 0)
  circle C1 centre (12, -55) radius 1.5
extrude "Extrude1" new body sketch "Preload M3x20 cap head" along normal blind 20 bodies "HARDWARE Preload M3x20 cap head"
work_plane "WorkPlane2" AlongDistance 57 ExtraOffset 0
sketch "Button head" plane through (0, 0, 57) normal (0, 0, 1) x axis (1, 0, 0)
  circle C1 centre (12, -55) radius 2.75
extrude "Extrude2" add sketch "Button head" along normal blind 3
work_plane "WorkPlane1" AlongDistance 18 ExtraOffset 0
sketch "Provisional stock spring installed envelope" plane through (0, 0, 18) normal (0, 0, 1) x axis (1, 0, 0)
  circle C1 centre (12, -55) radius 4.5
extrude "Extrude1" new body sketch "Provisional stock spring installed envelope" along normal blind 17 bodies "REFERENCE Stock spring OD9 wire1 free20 - rate and solid height assumed"
work_plane "WorkPlane2" AlongDistance 17.9 ExtraOffset 0
sketch "Stock spring nominal ID7" plane through (0, 0, 17.9) normal (0, 0, 1) x axis (1, 0, 0)
  circle C1 centre (12, -55) radius 3.5
extrude "Extrude2" cut sketch "Stock spring nominal ID7" along normal blind 17.2
work_plane "WorkPlane54" AlongDistance 36 ExtraOffset 0
sketch "Remove long sensor carriage supports" plane through (36, 0, 0) normal (1, 0, 0) x axis (0, 0, -1)
  line L1 (-46, 34) -> (-46, -34)
  line L2 (-84, 34) -> (-46, 34)
  line L3 (-84, -34) -> (-84, 34)
  line L4 (-46, -34) -> (-84, -34)
extrude "Extrude54" cut sketch "Remove long sensor carriage supports" along normal blind 44.1
work_plane "WorkPlane55" AlongDistance 36 ExtraOffset 0
sketch "Compact sensor support" plane through (36, 0, 0) normal (1, 0, 0) x axis (0, 0, -1)
  line L1 (-49, -18) -> (-49, -28)
  line L2 (-81, -18) -> (-49, -18)
  line L3 (-81, -28) -> (-81, -18)
  line L4 (-49, -28) -> (-81, -28)
extrude "Extrude55" add sketch "Compact sensor support" along normal blind 30.15
work_plane "WorkPlane56" AlongDistance -28.1 ExtraOffset 0
sketch "Compact carriage M3 insert" plane through (0, -28.1, 0) normal (0, 1, 0) x axis (1, 0, 0)
  circle C1 centre (60.15, -65) radius 2
extrude "Extrude56" cut sketch "Compact carriage M3 insert" along normal blind 6.8
work_plane "WorkPlane57" AlongDistance 36 ExtraOffset 0
sketch "Compact sensor support (1)" plane through (36, 0, 0) normal (1, 0, 0) x axis (0, 0, -1)
  line L1 (-49, 28) -> (-49, 18)
  line L2 (-81, 28) -> (-49, 28)
  line L3 (-81, 18) -> (-81, 28)
  line L4 (-49, 18) -> (-81, 18)
extrude "Extrude57" add sketch "Compact sensor support (1)" along normal blind 30.15
work_plane "WorkPlane58" AlongDistance 21.3 ExtraOffset 0
sketch "Compact carriage M3 insert (1)" plane through (0, 21.3, 0) normal (0, 1, 0) x axis (1, 0, 0)
  circle C1 centre (60.15, -65) radius 2
extrude "Extrude58" cut sketch "Compact carriage M3 insert (1)" along normal blind 6.8
work_plane "WorkPlane1" AlongDistance 66.15 ExtraOffset 0
sketch "Replaceable compact sensor panel" plane through (66.15, 0, 0) normal (1, 0, 0) x axis (0, 0, -1)
  line L1 (-46, 33) -> (-46, -33)
  line L2 (-84, 33) -> (-46, 33)
  line L3 (-84, -33) -> (-84, 33)
  line L4 (-46, -33) -> (-84, -33)
extrude "Extrude1" new body sketch "Replaceable compact sensor panel" along normal blind 3 bodies "P16 Compact adjustable RK097 mount"
work_plane "WorkPlane2" AlongDistance 54.15 ExtraOffset 0
sketch "Compact sliding ear" plane through (54.15, 0, 0) normal (1, 0, 0) x axis (0, 0, -1)
  line L1 (-58, -28) -> (-58, -33)
  line L2 (-72, -28) -> (-58, -28)
  line L3 (-72, -33) -> (-72, -28)
  line L4 (-58, -33) -> (-72, -33)
extrude "Extrude2" add sketch "Compact sliding ear" along normal blind 12.1
work_plane "WorkPlane3" AlongDistance -33.1 ExtraOffset 0
sketch "Axial adjustment slot" plane through (0, -33.1, 0) normal (0, 1, 0) x axis (1, 0, 0)
  line L1 (65.15, -63.3) -> (55.15, -63.3)
  line L2 (65.15, -66.7) -> (65.15, -63.3)
  line L3 (55.15, -66.7) -> (65.15, -66.7)
  line L4 (55.15, -63.3) -> (55.15, -66.7)
extrude "Extrude3" cut sketch "Axial adjustment slot" along normal blind 5.2
work_plane "WorkPlane4" AlongDistance -33.1 ExtraOffset 0
sketch "Rounded slot end" plane through (0, -33.1, 0) normal (0, 1, 0) x axis (1, 0, 0)
  circle C1 centre (55.15, -65) radius 1.7
extrude "Extrude4" cut sketch "Rounded slot end" along normal blind 5.2
work_plane "WorkPlane5" AlongDistance -33.1 ExtraOffset 0
sketch "Rounded slot end (1)" plane through (0, -33.1, 0) normal (0, 1, 0) x axis (1, 0, 0)
  circle C1 centre (65.15, -65) radius 1.7
extrude "Extrude5" cut sketch "Rounded slot end (1)" along normal blind 5.2
work_plane "WorkPlane1" AlongDistance -33 ExtraOffset 0
sketch "Compact carriage M3x12 -1" plane through (0, -33, 0) normal (0, 1, 0) x axis (1, 0, 0)
  circle C1 centre (60.15, -65) radius 1.5
extrude "Extrude1" new body sketch "Compact carriage M3x12 -1" along normal blind 12 bodies "HARDWARE Compact carriage M3x12 -1"
work_plane "WorkPlane2" AlongDistance -36 ExtraOffset 0
sketch "Button head" plane through (0, -36, 0) normal (0, 1, 0) x axis (1, 0, 0)
  circle C1 centre (60.15, -65) radius 2.75
extrude "Extrude2" add sketch "Button head" along normal blind 3
work_plane "WorkPlane6" AlongDistance 54.15 ExtraOffset 0
sketch "Compact sliding ear (1)" plane through (54.15, 0, 0) normal (1, 0, 0) x axis (0, 0, -1)
  line L1 (-58, 33) -> (-58, 28)
  line L2 (-72, 33) -> (-58, 33)
  line L3 (-72, 28) -> (-72, 33)
  line L4 (-58, 28) -> (-72, 28)
extrude "Extrude6" add sketch "Compact sliding ear (1)" along normal blind 12.1
work_plane "WorkPlane7" AlongDistance 27.9 ExtraOffset 0
sketch "Axial adjustment slot (1)" plane through (0, 27.9, 0) normal (0, 1, 0) x axis (1, 0, 0)
  line L1 (65.15, -63.3) -> (55.15, -63.3)
  line L2 (65.15, -66.7) -> (65.15, -63.3)
  line L3 (55.15, -66.7) -> (65.15, -66.7)
  line L4 (55.15, -63.3) -> (55.15, -66.7)
extrude "Extrude7" cut sketch "Axial adjustment slot (1)" along normal blind 5.2
work_plane "WorkPlane8" AlongDistance 27.9 ExtraOffset 0
sketch "Rounded slot end (2)" plane through (0, 27.9, 0) normal (0, 1, 0) x axis (1, 0, 0)
  circle C1 centre (55.15, -65) radius 1.7
extrude "Extrude8" cut sketch "Rounded slot end (2)" along normal blind 5.2
work_plane "WorkPlane9" AlongDistance 27.9 ExtraOffset 0
sketch "Rounded slot end (3)" plane through (0, 27.9, 0) normal (0, 1, 0) x axis (1, 0, 0)
  circle C1 centre (65.15, -65) radius 1.7
extrude "Extrude9" cut sketch "Rounded slot end (3)" along normal blind 5.2
work_plane "WorkPlane1" AlongDistance 21 ExtraOffset 0
sketch "Compact carriage M3x12 1" plane through (0, 21, 0) normal (0, 1, 0) x axis (1, 0, 0)
  circle C1 centre (60.15, -65) radius 1.5
extrude "Extrude1" new body sketch "Compact carriage M3x12 1" along normal blind 12 bodies "HARDWARE Compact carriage M3x12 1"
work_plane "WorkPlane2" AlongDistance 33 ExtraOffset 0
sketch "Button head" plane through (0, 33, 0) normal (0, 1, 0) x axis (1, 0, 0)
  circle C1 centre (60.15, -65) radius 2.75
extrude "Extrude2" add sketch "Button head" along normal blind 3
work_plane "WorkPlane10" AlongDistance 66.05 ExtraOffset 0
sketch "Provisional M7 sensor bushing opening" plane through (66.05, 0, 0) normal (1, 0, 0) x axis (0, 0, -1)
  circle C1 centre (-65, 0) radius 3.6
extrude "Extrude10" cut sketch "Provisional M7 sensor bushing opening" along normal blind 3.2
work_plane "WorkPlane11" AlongDistance 66.05 ExtraOffset 0
sketch "Sensor body retention option" plane through (66.05, 0, 0) normal (1, 0, 0) x axis (0, 0, -1)
  line L1 (-59, -7) -> (-59, -9)
  line L2 (-71, -7) -> (-59, -7)
  line L3 (-71, -9) -> (-71, -7)
  line L4 (-59, -9) -> (-71, -9)
extrude "Extrude11" cut sketch "Sensor body retention option" along normal blind 3.2
work_plane "WorkPlane12" AlongDistance 66.05 ExtraOffset 0
sketch "Sensor body retention option (1)" plane through (66.05, 0, 0) normal (1, 0, 0) x axis (0, 0, -1)
  line L1 (-59, 9) -> (-59, 7)
  line L2 (-71, 9) -> (-59, 9)
  line L3 (-71, 7) -> (-71, 9)
  line L4 (-59, 7) -> (-71, 7)
extrude "Extrude12" cut sketch "Sensor body retention option (1)" along normal blind 3.2
work_plane "WorkPlane1" AlongDistance 41 ExtraOffset 0
sketch "Compact Oldham disc" plane through (41, 0, 0) normal (1, 0, 0) x axis (0, 0, -1)
  circle C1 centre (-65, 0) radius 12
extrude "Extrude1" new body sketch "Compact Oldham disc" along normal blind 8 bodies "P18 Compact floating coupling disc"
work_plane "WorkPlane2" AlongDistance 40.9 ExtraOffset 0
sketch "Input groove 4.2 mm" plane through (40.9, 0, 0) normal (1, 0, 0) x axis (0, 0, -1)
  line L1 (-62.9, 13) -> (-62.9, -13)
  line L2 (-67.1, 13) -> (-62.9, 13)
  line L3 (-67.1, -13) -> (-67.1, 13)
  line L4 (-62.9, -13) -> (-67.1, -13)
extrude "Extrude2" cut sketch "Input groove 4.2 mm" along normal blind 2.9
work_plane "WorkPlane3" AlongDistance 46.2 ExtraOffset 0
sketch "Output groove 4.2 mm" plane through (46.2, 0, 0) normal (1, 0, 0) x axis (0, 0, -1)
  line L1 (-52, 2.1) -> (-52, -2.1)
  line L2 (-78, 2.1) -> (-52, 2.1)
  line L3 (-78, -2.1) -> (-78, 2.1)
  line L4 (-52, -2.1) -> (-78, -2.1)
extrude "Extrude3" cut sketch "Output groove 4.2 mm" along normal blind 2.9
work_plane "WorkPlane1" AlongDistance 49.65 ExtraOffset 0
sketch "Single split output hub" plane through (49.65, 0, 0) normal (1, 0, 0) x axis (0, 0, -1)
  circle C1 centre (-65, 0) radius 7
extrude "Extrude1" new body sketch "Single split output hub" along normal blind 9 bodies "P19 Compact one-piece sensor clamp"
work_plane "WorkPlane2" AlongDistance 49.65 ExtraOffset 0
sketch "One-screw clamp boss" plane through (49.65, 0, 0) normal (1, 0, 0) x axis (0, 0, -1)
  line L1 (-69, 9) -> (-69, -9)
  line L2 (-78, 9) -> (-69, 9)
  line L3 (-78, -9) -> (-78, 9)
  line L4 (-69, -9) -> (-78, -9)
extrude "Extrude2" add sketch "One-screw clamp boss" along normal blind 9
work_plane "WorkPlane3" AlongDistance 46.65 ExtraOffset 0
sketch "Output drive prongs" plane through (46.65, 0, 0) normal (1, 0, 0) x axis (0, 0, -1)
  line L1 (-57, 2) -> (-57, -2)
  line L2 (-73, 2) -> (-57, 2)
  line L3 (-73, -2) -> (-73, 2)
  line L4 (-57, -2) -> (-73, -2)
extrude "Extrude3" add sketch "Output drive prongs" along normal blind 3.1
work_plane "WorkPlane4" AlongDistance 46.55 ExtraOffset 0
sketch "Provisional 6 mm sensor through socket" plane through (46.55, 0, 0) normal (1, 0, 0) x axis (0, 0, -1)
  circle C1 centre (-65, 0) radius 3.1
extrude "Extrude4" cut sketch "Provisional 6 mm sensor through socket" along normal blind 12.2
work_plane "WorkPlane5" AlongDistance 46.55 ExtraOffset 0
sketch "Elastic clamp split" plane through (46.55, 0, 0) normal (1, 0, 0) x axis (0, 0, -1)
  line L1 (-65, 0.2) -> (-65, -0.2)
  line L2 (-79, 0.2) -> (-65, 0.2)
  line L3 (-79, -0.2) -> (-79, 0.2)
  line L4 (-65, -0.2) -> (-79, -0.2)
extrude "Extrude5" cut sketch "Elastic clamp split" along normal blind 12.2
work_plane "WorkPlane6" AlongDistance -9.1 ExtraOffset 0
sketch "Accessible CNC Kitchen insert pocket" plane through (0, -9.1, 0) normal (0, 1, 0) x axis (1, 0, 0)
  circle C1 centre (54.15, -73) radius 2
extrude "Extrude6" cut sketch "Accessible CNC Kitchen insert pocket" along normal blind 9
work_plane "WorkPlane7" AlongDistance 0.1 ExtraOffset 0
sketch "Clamp screw clearance" plane through (0, 0.1, 0) normal (0, 1, 0) x axis (1, 0, 0)
  circle C1 centre (54.15, -73) radius 1.7
extrude "Extrude7" cut sketch "Clamp screw clearance" along normal blind 9
work_plane "WorkPlane1" AlongDistance -7 ExtraOffset 0
sketch "Compact sensor clamp M3x16" plane through (0, -7, 0) normal (0, 1, 0) x axis (1, 0, 0)
  circle C1 centre (54.15, -73) radius 1.5
extrude "Extrude1" new body sketch "Compact sensor clamp M3x16" along normal blind 16 bodies "HARDWARE Compact sensor clamp M3x16"
work_plane "WorkPlane2" AlongDistance 9 ExtraOffset 0
sketch "Button head" plane through (0, 9, 0) normal (0, 1, 0) x axis (1, 0, 0)
  circle C1 centre (54.15, -73) radius 2.75
extrude "Extrude2" add sketch "Button head" along normal blind 3
work_plane "WorkPlane59" AlongDistance 36 ExtraOffset 0
sketch "Restore cam service path beneath compact rails" plane through (36, 0, 0) normal (1, 0, 0) x axis (0, 0, -1)
  line L1 (-48.9, -18) -> (-48.9, -28)
  line L2 (-56, -18) -> (-48.9, -18)
  line L3 (-56, -28) -> (-56, -18)
  line L4 (-48.9, -28) -> (-56, -28)
extrude "Extrude59" cut sketch "Restore cam service path beneath compact rails" along normal blind 30.25
work_plane "WorkPlane60" AlongDistance 36 ExtraOffset 0
sketch "Restore cam service path beneath compact rails (1)" plane through (36, 0, 0) normal (1, 0, 0) x axis (0, 0, -1)
  line L1 (-48.9, 28) -> (-48.9, 18)
  line L2 (-56, 28) -> (-48.9, 28)
  line L3 (-56, 18) -> (-56, 28)
  line L4 (-48.9, 18) -> (-56, 18)
extrude "Extrude60" cut sketch "Restore cam service path beneath compact rails (1)" along normal blind 30.25
work_plane "WorkPlane66" AlongDistance 54.9 ExtraOffset 0
sketch "Support-free horizontal rail hole roof" plane through (0, 0, 54.9) normal (0, 0, 1) x axis (1, 0, 0)
  line L1 (-28.0908, -83.0908) -> (-28.0908, -86.9092)
  line L2 (-26.1816, -85) -> (-28.0908, -83.0908)
  line L3 (-28.0908, -86.9092) -> (-26.1816, -85)
extrude "Extrude66" cut sketch "Support-free horizontal rail hole roof" along normal blind 9.2
work_plane "WorkPlane67" AlongDistance 54.9 ExtraOffset 0
sketch "Support-free horizontal rail hole roof (1)" plane through (0, 0, 54.9) normal (0, 0, 1) x axis (1, 0, 0)
  line L1 (-28.0908, 86.9092) -> (-28.0908, 83.0908)
  line L2 (-26.1816, 85) -> (-28.0908, 86.9092)
  line L3 (-28.0908, 83.0908) -> (-26.1816, 85)
extrude "Extrude67" cut sketch "Support-free horizontal rail hole roof (1)" along normal blind 9.2
work_plane "WorkPlane61" AlongDistance 54.9 ExtraOffset 0
sketch "Support-free horizontal rail hole roof" plane through (0, 0, 54.9) normal (0, 0, 1) x axis (1, 0, 0)
  line L1 (31.9092, -83.0908) -> (31.9092, -86.9092)
  line L2 (33.8184, -85) -> (31.9092, -83.0908)
  line L3 (31.9092, -86.9092) -> (33.8184, -85)
extrude "Extrude61" cut sketch "Support-free horizontal rail hole roof" along normal blind 9.2
work_plane "WorkPlane62" AlongDistance 54.9 ExtraOffset 0
sketch "Support-free horizontal rail hole roof (1)" plane through (0, 0, 54.9) normal (0, 0, 1) x axis (1, 0, 0)
  line L1 (31.9092, 86.9092) -> (31.9092, 83.0908)
  line L2 (33.8184, 85) -> (31.9092, 86.9092)
  line L3 (31.9092, 83.0908) -> (33.8184, 85)
extrude "Extrude62" cut sketch "Support-free horizontal rail hole roof (1)" along normal blind 9.2
work_plane "WorkPlane14" AlongDistance 4 ExtraOffset 0
sketch "Reinforced roof over support-free pivot bore" plane through (4, 0, 0) normal (1, 0, 0) x axis (0, 0, -1)
  line L1 (-17.9, -29) -> (-17.9, -41)
  line L2 (-20, -29) -> (-17.9, -29)
  line L3 (-20, -41) -> (-20, -29)
  line L4 (-17.9, -41) -> (-20, -41)
extrude "Extrude14" add sketch "Reinforced roof over support-free pivot bore" along normal blind 3
work_plane "WorkPlane15" AlongDistance 4 ExtraOffset 0
sketch "Flat print foot below roller cheek" plane through (4, 0, 0) normal (1, 0, 0) x axis (0, 0, -1)
  line L1 (-6, 6) -> (-6, -6)
  line L2 (-12, 6) -> (-6, 6)
  line L3 (-12, -6) -> (-12, 6)
  line L4 (-6, -6) -> (-12, -6)
extrude "Extrude15" add sketch "Flat print foot below roller cheek" along normal blind 3
work_plane "WorkPlane16" AlongDistance 17 ExtraOffset 0
sketch "Reinforced roof over support-free pivot bore (1)" plane through (17, 0, 0) normal (1, 0, 0) x axis (0, 0, -1)
  line L1 (-17.9, -29) -> (-17.9, -41)
  line L2 (-20, -29) -> (-17.9, -29)
  line L3 (-20, -41) -> (-20, -29)
  line L4 (-17.9, -41) -> (-20, -41)
extrude "Extrude16" add sketch "Reinforced roof over support-free pivot bore (1)" along normal blind 3
work_plane "WorkPlane17" AlongDistance 17 ExtraOffset 0
sketch "Flat print foot below roller cheek (1)" plane through (17, 0, 0) normal (1, 0, 0) x axis (0, 0, -1)
  line L1 (-6, 6) -> (-6, -6)
  line L2 (-12, 6) -> (-6, 6)
  line L3 (-12, -6) -> (-12, 6)
  line L4 (-6, -6) -> (-12, -6)
extrude "Extrude17" add sketch "Flat print foot below roller cheek (1)" along normal blind 3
